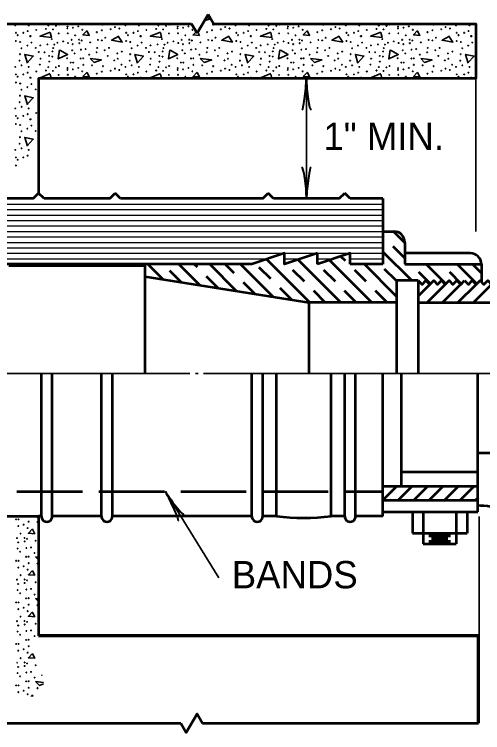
# Model space of a CAD drawing. Extents: x -1 to 679, y 0 to 440.
# Drawn here: x 158 to 200.8, y 293.5 to 359.2 of the extents above; entities that cross this region are included whole.
import ezdxf

# ---------------------------------------------------------------- set-up
doc = ezdxf.new("R2010")
doc.units = 0
doc.linetypes.add('LONG_DASHED', pattern=[7.5, 6, -1.5])
doc.linetypes.add('SHORT_DASHED', pattern=[2.7, 1.5, -1.2])
doc.layers.add('1', color=7, linetype='Continuous', lineweight=35)

msp = doc.modelspace()

# ---------------------------------------------------------------- linework, layer by layer
at = {"layer": '1', "lineweight": 53}
for p, q in [((174.684, 357.51), (175.684, 359.242)), ((176.184, 358.376), (175.684, 359.242)), ((153.184, 358.376), (174.184, 358.376)), ((174.684, 357.51), (174.184, 358.376)), ((159.684, 342.376), (160.184, 342.876)), ((160.684, 342.376), (160.184, 342.876)), ((166.684, 342.376), (167.184, 342.876)), ((167.684, 342.376), (167.184, 342.876)), ((180.684, 342.376), (181.184, 342.876)), ((181.684, 342.376), (181.184, 342.876)), ((187.684, 342.376), (188.184, 342.876)), ((188.684, 342.376), (188.184, 342.876)), ((159.684, 342.376), (146.684, 342.376)), ((166.684, 342.376), (160.684, 342.376)), ((180.684, 342.376), (167.684, 342.376)), ((187.684, 342.376), (181.684, 342.376)), ((191.684, 342.376), (188.684, 342.376)), ((191.684, 342.376), (191.684, 336.376)), ((191.684, 339.376), (192.684, 339.376)), ((193.673, 338.337), (192.637, 339.373)), ((193.684, 338.376), (193.684, 336.376)), ((185.684, 336.376), (185.684, 337.376)), ((194.308, 334.873), (191.673, 337.508)), ((199.684, 337.376), (193.684, 337.376)), ((184.995, 332.873), (181.039, 336.828)), ((187.823, 332.873), (183.911, 336.786)), ((190.652, 332.873), (186.782, 336.743)), ((179.684, 336.376), (147.684, 336.376)), ((157.463, 336.251), (169.905, 336.251)), ((169.905, 336.251), (169.905, 326.376)), ((171.572, 334.983), (170.181, 336.373)), ((174.932, 334.45), (173.01, 336.373)), ((178.293, 333.918), (175.838, 336.373)), ((181.653, 333.386), (178.666, 336.373)), ((191.684, 336.376), (188.684, 336.376)), ((192.894, 333.459), (189.98, 336.373)), ((193.684, 336.376), (200.684, 336.376)), ((197.43, 334.58), (195.637, 336.373)), ((200.258, 334.58), (198.465, 336.373)), ((200.684, 336.376), (200.684, 334.754)), ((169.905, 335.251), (184.905, 332.876)), ((194.905, 334.876), (192.905, 334.876)), ((192.905, 334.876), (192.905, 326.376)), ((194.905, 334.876), (194.905, 326.376)), ((198.795, 334.522), (199.148, 334.876)), ((195.958, 334.515), (194.907, 333.464)), ((197.372, 334.515), (195.716, 332.859)), ((198.787, 334.515), (197.13, 332.859)), ((200.201, 334.515), (198.544, 332.859)), ((201.615, 334.515), (199.958, 332.859)), ((192.905, 332.876), (184.905, 332.876)), ((184.905, 332.876), (184.905, 326.376)), ((194.905, 332.876), (224.905, 332.876)), ((160.434, 313.316), (160.434, 326.376)), ((161.434, 313.316), (161.434, 326.376)), ((165.934, 313.316), (165.934, 326.376)), ((166.934, 313.316), (166.934, 326.376)), ((179.684, 313.316), (179.684, 326.376)), ((180.684, 313.316), (180.684, 326.376)), ((181.934, 313.316), (181.934, 326.376)), ((186.934, 313.316), (186.934, 326.376)), ((188.184, 313.316), (188.184, 326.376)), ((189.184, 313.316), (189.184, 326.376)), ((191.684, 313.316), (191.684, 326.376)), ((193.369, 316.034), (193.369, 326.376)), ((200.369, 316.327), (200.369, 326.376)), ((200.434, 319.126), (222.934, 319.126)), ((200.369, 317.336), (193.369, 317.336)), ((200.369, 313.731), (200.369, 316.327)), ((191.666, 314.784), (192.916, 316.034)), ((200.434, 316.034), (191.684, 316.034)), ((193.08, 314.784), (194.33, 316.034)), ((194.494, 314.784), (195.744, 316.034)), ((195.909, 314.784), (197.159, 316.034)), ((197.323, 314.784), (198.573, 316.034)), ((198.737, 314.784), (199.987, 316.034)), ((200.151, 314.784), (200.434, 315.067)), ((191.684, 314.784), (200.434, 314.784)), ((191.684, 313.731), (200.369, 313.731)), ((194.369, 313.778), (194.369, 311.778)), ((195.369, 313.778), (195.369, 310.778)), ((198.369, 313.778), (198.369, 310.778)), ((199.369, 313.778), (199.369, 311.778)), ((160.434, 313.316), (160.184, 313.316)), ((165.934, 313.316), (161.434, 313.316)), ((179.684, 313.316), (166.934, 313.316)), ((181.934, 313.316), (180.684, 313.316)), ((188.184, 313.316), (186.934, 313.316)), ((191.684, 313.316), (189.184, 313.316)), ((194.369, 311.778), (199.369, 311.778)), ((195.869, 311.528), (197.869, 311.528)), ((195.869, 311.028), (197.869, 311.028)), ((196.119, 311.278), (197.619, 311.278)), ((195.369, 310.778), (198.369, 310.778)), ((140.184, 294.376), (173.184, 294.376)), ((175.184, 294.376), (200.409, 294.376))]:
    msp.add_line(p, q, dxfattribs=at)
at = {"layer": '1'}
for p, q in [((175.508, 358.936), (175.886, 358.893)), ((161.343, 353.376), (161.256, 353.778)), ((171.423, 353.376), (171.336, 353.778)), ((181.503, 353.376), (181.416, 353.778)), ((191.583, 353.376), (191.496, 353.778)), ((167.516, 353.438), (167.402, 353.376)), ((167.528, 353.376), (167.476, 353.458)), ((177.596, 353.438), (177.482, 353.376)), ((177.608, 353.376), (177.556, 353.458)), ((184.684, 342.376), (184.684, 353.376)), ((187.676, 353.438), (187.562, 353.376)), ((187.688, 353.376), (187.636, 353.458)), ((197.756, 353.438), (197.642, 353.376)), ((197.768, 353.376), (197.716, 353.458)), ((200.184, 353.376), (200.184, 339.376)), ((142.088, 326.376), (174.026, 326.376)), ((174.526, 326.376), (174.776, 326.376)), ((175.276, 326.376), (181.934, 326.376)), ((171.782, 315.566), (176.655, 307.674)), ((160.184, 313.115), (159.984, 313.316)), ((200.475, 302.376), (200.475, 313.277)), ((159.904, 309.596), (160.184, 309.563)), ((160.184, 309.315), (159.904, 309.596)), ((159.904, 305.796), (160.184, 305.763)), ((160.184, 305.515), (159.904, 305.796)), ((159.904, 298.196), (160.626, 298.112)), ((159.624, 296.956), (159.484, 296.808)), ((159.668, 296.828), (159.624, 296.916))]:
    msp.add_line(p, q, dxfattribs=at)
at = {"layer": '1', "lineweight": 25}
for p, q in [((135.684, 341.876), (191.684, 341.876)), ((135.684, 341.376), (191.684, 341.376)), ((135.684, 340.876), (191.684, 340.876)), ((135.684, 340.376), (191.684, 340.376)), ((135.684, 339.876), (191.684, 339.876)), ((135.684, 339.376), (191.684, 339.376)), ((135.684, 338.876), (191.684, 338.876)), ((135.684, 338.376), (191.684, 338.376)), ((135.684, 337.876), (191.684, 337.876)), ((135.684, 337.376), (191.684, 337.376)), ((146.184, 336.876), (181.184, 336.876)), ((182.684, 336.876), (184.184, 336.876)), ((185.684, 336.876), (187.184, 336.876)), ((188.684, 336.876), (191.684, 336.876))]:
    msp.add_line(p, q, dxfattribs=at)
at = {"layer": '1', "linetype": 'SHORT_DASHED', "lineweight": 53}
for p, q in [((193.673, 336.923), (191.673, 338.923)), ((192.066, 332.873), (187.843, 337.096)), ((173.252, 334.716), (171.595, 336.373)), ((176.612, 334.184), (174.424, 336.373)), ((179.973, 333.652), (177.252, 336.373)), ((183.333, 333.12), (179.979, 336.475)), ((186.409, 332.873), (182.85, 336.432)), ((189.237, 332.873), (185.721, 336.389)), ((192.894, 334.873), (191.394, 336.373)), ((196.016, 334.58), (194.223, 336.373)), ((198.844, 334.58), (197.051, 336.373)), ((200.673, 335.579), (199.88, 336.373))]:
    msp.add_line(p, q, dxfattribs=at)
at = {"layer": '1', "linetype": 'LONG_DASHED', "lineweight": 53}
msp.add_line((135.684, 315.566), (191.684, 315.566), dxfattribs=at)
at = {"layer": '1', "lineweight": 70}
for p, q in [((200.409, 302.376), (160.184, 302.376)), ((200.409, 294.376), (200.409, 302.376))]:
    msp.add_line(p, q, dxfattribs=at)
at = {"layer": '1', "lineweight": 53}
for points in [[(176.184, 358.376), (200.184, 358.376), (200.184, 353.376), (160.184, 353.376), (160.184, 342.876)], [(185.684, 337.376), (182.684, 336.376), (182.684, 337.376), (179.684, 336.376)], [(188.684, 336.376), (188.684, 337.376), (185.684, 336.376)], [(194.905, 334.876), (195.259, 334.522), (195.613, 334.876), (195.966, 334.522), (196.32, 334.876), (196.673, 334.522), (197.027, 334.876), (197.38, 334.522), (197.734, 334.876), (198.088, 334.522), (198.441, 334.876), (198.795, 334.522)], [(199.148, 334.876), (199.502, 334.522), (199.856, 334.876), (200.209, 334.522), (200.563, 334.876), (200.916, 334.522), (201.27, 334.876), (201.624, 334.522), (201.977, 334.876), (202.331, 334.522), (202.684, 334.876)], [(149.22, 313.316), (160.184, 313.316), (160.184, 302.376)], [(173.184, 294.376), (173.684, 293.51), (174.684, 295.242), (175.184, 294.376)]]:
    msp.add_lwpolyline(points, dxfattribs=at)
at = {"layer": '1'}
for points in [[(175.915, 358.842), (175.336, 358.638), (175.336, 358.638)], [(161.256, 357.618), (160.316, 357.238), (161.356, 357.118), (161.256, 357.578)], [(164.616, 357.758), (164.236, 357.358), (164.816, 357.318), (164.616, 357.718)], [(171.336, 357.618), (170.396, 357.238), (171.436, 357.118), (171.336, 357.578)], [(174.6, 357.657), (174.316, 357.358), (174.896, 357.318), (174.746, 357.617)], [(181.416, 357.618), (180.476, 357.238), (181.516, 357.118), (181.416, 357.578)], [(184.776, 357.758), (184.396, 357.358), (184.976, 357.318), (184.776, 357.718)], [(191.496, 357.618), (190.556, 357.238), (191.596, 357.118), (191.496, 357.578)], [(194.856, 357.758), (194.476, 357.358), (195.056, 357.318), (194.856, 357.718)], [(167.516, 357.238), (166.856, 356.878), (167.836, 356.698), (167.476, 357.258)], [(177.596, 357.238), (176.936, 356.878), (177.916, 356.698), (177.556, 357.258)], [(187.676, 357.238), (187.016, 356.878), (187.996, 356.698), (187.636, 357.258)], [(197.756, 357.238), (197.096, 356.878), (198.076, 356.698), (197.716, 357.258)], [(162.136, 355.978), (162.836, 355.578), (161.976, 355.158), (162.096, 355.998)], [(172.216, 355.978), (172.916, 355.578), (172.056, 355.158), (172.176, 355.998)], [(182.296, 355.978), (182.996, 355.578), (182.136, 355.158), (182.256, 355.998)], [(192.376, 355.978), (193.076, 355.578), (192.216, 355.158), (192.336, 355.998)], [(159.156, 354.778), (158.916, 355.578), (159.696, 355.418), (159.136, 354.818)], [(169.236, 354.778), (168.996, 355.578), (169.776, 355.418), (169.216, 354.818)], [(179.316, 354.778), (179.076, 355.578), (179.856, 355.418), (179.296, 354.818)], [(189.396, 354.778), (189.156, 355.578), (189.936, 355.418), (189.376, 354.818)], [(199.476, 354.778), (199.236, 355.578), (200.016, 355.418), (199.456, 354.818)], [(161.256, 353.818), (160.316, 353.438), (160.854, 353.376)], [(164.616, 353.958), (164.236, 353.558), (164.816, 353.518), (164.616, 353.918)], [(171.336, 353.818), (170.396, 353.438), (170.934, 353.376)], [(174.696, 353.958), (174.316, 353.558), (174.896, 353.518), (174.696, 353.918)], [(181.416, 353.818), (180.476, 353.438), (181.014, 353.376)], [(184.776, 353.958), (184.396, 353.558), (184.976, 353.518), (184.776, 353.918)], [(191.496, 353.818), (190.556, 353.438), (191.094, 353.376)], [(194.856, 353.958), (194.476, 353.558), (195.056, 353.518), (194.856, 353.918)], [(159.156, 350.978), (158.916, 351.778), (159.696, 351.618), (159.136, 351.018)], [(159.156, 347.178), (158.916, 347.978), (159.696, 347.818), (159.136, 347.218)], [(181.934, 326.376), (194.905, 326.376), (200.434, 326.376), (208.434, 326.376)], [(159.624, 312.156), (159.244, 311.756), (159.824, 311.716), (159.624, 312.116)], [(159.624, 308.356), (159.244, 307.956), (159.824, 307.916), (159.624, 308.316)], [(159.624, 304.556), (159.244, 304.156), (159.824, 304.116), (159.624, 304.516)], [(159.624, 300.756), (159.244, 300.356), (159.824, 300.316), (159.624, 300.716)], [(160.641, 297.969), (160.264, 297.836), (159.904, 298.196)]]:
    msp.add_lwpolyline(points, dxfattribs=at)
for points in [[(164.896, 355.198), (165.936, 355.078), (165.256, 354.838)], [(174.976, 355.198), (176.016, 355.078), (175.336, 354.838)], [(185.056, 355.198), (186.096, 355.078), (185.416, 354.838)], [(195.136, 355.198), (196.176, 355.078), (195.496, 354.838)]]:
    msp.add_lwpolyline(points, close=True, dxfattribs=at)
for centre in [(158.044, 358.234), (159.277, 358.234), (161.066, 358.221), (162.046, 358.314), (166.07, 358.301), (168.124, 358.234), (169.357, 358.234), (171.146, 358.221), (172.126, 358.314), (176.15, 358.301), (178.204, 358.234), (179.437, 358.234), (181.226, 358.221), (182.206, 358.314), (186.23, 358.301), (188.284, 358.234), (189.517, 358.234), (191.306, 358.221), (192.286, 358.314), (196.31, 358.301), (198.364, 358.234), (199.597, 358.234), (159.184, 357.709), (159.966, 357.815), (160.854, 357.908), (161.49, 357.868), (161.768, 358.195), (162.815, 357.961), (162.828, 358.128), (163.319, 358.014), (163.809, 358.142), (164.175, 357.828), (165.513, 357.616), (165.964, 357.789), (166.772, 357.881), (167.17, 358.075), (167.567, 357.948), (169.264, 357.709), (170.046, 357.815), (170.934, 357.908), (171.57, 357.868), (171.848, 358.195), (172.895, 357.961), (172.908, 358.128), (173.399, 358.014), (173.889, 358.142), (174.255, 357.828), (175.593, 357.616), (176.044, 357.789), (176.852, 357.881), (177.25, 358.075), (177.647, 357.948), (179.344, 357.709), (180.126, 357.815), (181.014, 357.908), (181.65, 357.868), (181.928, 358.195), (182.975, 357.961), (182.988, 358.128), (183.479, 358.014), (183.969, 358.142), (184.335, 357.828), (185.673, 357.616), (186.124, 357.789), (186.932, 357.881), (187.33, 358.075), (187.727, 357.948), (189.424, 357.709), (190.206, 357.815), (191.094, 357.908), (191.73, 357.868), (192.008, 358.195), (193.055, 357.961), (193.068, 358.128), (193.559, 358.014), (194.049, 358.142), (194.415, 357.828), (195.753, 357.616), (196.204, 357.789), (197.012, 357.881), (197.41, 358.075), (197.807, 357.948), (199.504, 357.709), (158.11, 357.55), (158.269, 357.338), (158.786, 357.55), (159.409, 357.245), (159.462, 357.245), (161.384, 356.98), (162.02, 357.497), (162.855, 357.51), (163.199, 356.914), (163.531, 357.325), (163.889, 356.927), (165.619, 356.9), (166.282, 357.099), (168.19, 357.55), (168.349, 357.338), (168.866, 357.55), (169.489, 357.245), (169.542, 357.245), (171.464, 356.98), (172.1, 357.497), (172.935, 357.51), (173.279, 356.914), (173.611, 357.325), (173.969, 356.927), (175.699, 356.9), (176.362, 357.099), (178.27, 357.55), (178.429, 357.338), (178.946, 357.55), (179.569, 357.245), (179.622, 357.245), (181.544, 356.98), (182.18, 357.497), (183.015, 357.51), (183.359, 356.914), (183.691, 357.325), (184.049, 356.927), (185.779, 356.9), (186.442, 357.099), (188.35, 357.55), (188.509, 357.338), (189.026, 357.55), (189.649, 357.245), (189.702, 357.245), (191.624, 356.98), (192.26, 357.497), (193.095, 357.51), (193.439, 356.914), (193.771, 357.325), (194.129, 356.927), (195.859, 356.9), (196.522, 357.099), (198.43, 357.55), (198.589, 357.338), (199.106, 357.55), (199.729, 357.245), (199.782, 357.245), (158.11, 356.808), (158.495, 356.715), (159.157, 356.383), (159.528, 356.662), (160.337, 356.397), (160.986, 356.489), (161.622, 356.476), (161.901, 356.648), (162.431, 356.768), (162.881, 356.622), (163.306, 356.516), (163.902, 356.609), (164.122, 356.847), (164.903, 356.675), (165.964, 356.861), (168.19, 356.808), (168.575, 356.715), (169.237, 356.383), (169.608, 356.662), (170.417, 356.397), (171.066, 356.489), (171.702, 356.476), (171.981, 356.648), (172.511, 356.768), (172.961, 356.622), (173.386, 356.516), (173.982, 356.609), (174.202, 356.847), (174.983, 356.675), (176.044, 356.861), (178.27, 356.808), (178.655, 356.715), (179.317, 356.383), (179.688, 356.662), (180.497, 356.397), (181.146, 356.489), (181.782, 356.476), (182.061, 356.648), (182.591, 356.768), (183.041, 356.622), (183.466, 356.516), (184.062, 356.609), (184.282, 356.847), (185.063, 356.675), (186.124, 356.861), (188.35, 356.808), (188.735, 356.715), (189.397, 356.383), (189.768, 356.662), (190.577, 356.397), (191.226, 356.489), (191.862, 356.476), (192.141, 356.648), (192.671, 356.768), (193.121, 356.622), (193.546, 356.516), (194.142, 356.609), (194.362, 356.847), (195.143, 356.675), (196.204, 356.861), (198.43, 356.808), (198.815, 356.715), (199.477, 356.383), (199.848, 356.662), (158.481, 355.601), (158.614, 356.145), (159.926, 356.171), (160.204, 355.8), (160.721, 355.773), (161.45, 355.853), (161.516, 356.158), (163.252, 355.959), (163.478, 355.667), (164.061, 356.012), (164.479, 356.065), (165.487, 355.773), (165.54, 356.171), (166.229, 355.959), (166.626, 356.171), (167.382, 355.667), (167.793, 355.84), (168.561, 355.601), (168.694, 356.145), (170.006, 356.171), (170.284, 355.8), (170.801, 355.773), (171.53, 355.853), (171.596, 356.158), (173.332, 355.959), (173.558, 355.667), (174.141, 356.012), (174.559, 356.065), (175.567, 355.773), (175.62, 356.171), (176.309, 355.959), (176.706, 356.171), (177.462, 355.667), (177.873, 355.84), (178.641, 355.601), (178.774, 356.145), (180.086, 356.171), (180.364, 355.8), (180.881, 355.773), (181.61, 355.853), (181.676, 356.158), (183.412, 355.959), (183.638, 355.667), (184.221, 356.012), (184.639, 356.065), (185.647, 355.773), (185.7, 356.171), (186.389, 355.959), (186.786, 356.171), (187.542, 355.667), (187.953, 355.84), (188.721, 355.601), (188.854, 356.145), (190.166, 356.171), (190.444, 355.8), (190.961, 355.773), (191.69, 355.853), (191.756, 356.158), (193.492, 355.959), (193.718, 355.667), (194.301, 356.012), (194.719, 356.065), (195.727, 355.773), (195.78, 356.171), (196.469, 355.959), (196.866, 356.171), (197.622, 355.667), (198.033, 355.84), (198.801, 355.601), (198.934, 356.145), (158.442, 355.005), (160.363, 355.19), (161.145, 355.442), (161.437, 355.376), (162.789, 355.23), (164.041, 355.201), (164.267, 355.217), (164.811, 355.548), (166.507, 355.442), (167.104, 355.031), (167.422, 355.177), (168.522, 355.005), (170.443, 355.19), (171.225, 355.442), (171.517, 355.376), (172.869, 355.23), (174.121, 355.201), (174.347, 355.217), (174.891, 355.548), (176.587, 355.442), (177.184, 355.031), (177.502, 355.177), (178.602, 355.005), (180.523, 355.19), (181.305, 355.442), (181.597, 355.376), (182.949, 355.23), (184.201, 355.201), (184.427, 355.217), (184.971, 355.548), (186.667, 355.442), (187.264, 355.031), (187.582, 355.177), (188.682, 355.005), (190.603, 355.19), (191.385, 355.442), (191.677, 355.376), (193.029, 355.23), (194.281, 355.201), (194.507, 355.217), (195.051, 355.548), (196.747, 355.442), (197.344, 355.031), (197.662, 355.177), (198.762, 355.005), (158.044, 354.434), (158.627, 354.58), (159.277, 354.434), (160.297, 354.647), (161.066, 354.421), (161.159, 354.925), (161.768, 354.395), (162.046, 354.514), (162.828, 354.328), (163.12, 354.832), (163.345, 354.832), (163.809, 354.342), (164.267, 354.62), (165.076, 354.58), (166.07, 354.501), (167.17, 354.275), (167.766, 354.633), (168.124, 354.434), (168.707, 354.58), (169.357, 354.434), (170.377, 354.647), (171.146, 354.421), (171.239, 354.925), (171.848, 354.395), (172.126, 354.514), (172.908, 354.328), (173.2, 354.832), (173.425, 354.832), (173.889, 354.342), (174.347, 354.62), (175.156, 354.58), (176.15, 354.501), (177.25, 354.275), (177.846, 354.633), (178.204, 354.434), (178.787, 354.58), (179.437, 354.434), (180.457, 354.647), (181.226, 354.421), (181.319, 354.925), (181.928, 354.395), (182.206, 354.514), (182.988, 354.328), (183.28, 354.832), (183.505, 354.832), (183.969, 354.342), (184.427, 354.62), (185.236, 354.58), (186.23, 354.501), (187.33, 354.275), (187.926, 354.633), (188.284, 354.434), (188.867, 354.58), (189.517, 354.434), (190.537, 354.647), (191.306, 354.421), (191.399, 354.925), (192.008, 354.395), (192.286, 354.514), (193.068, 354.328), (193.36, 354.832), (193.585, 354.832), (194.049, 354.342), (194.507, 354.62), (195.316, 354.58), (196.31, 354.501), (197.41, 354.275), (198.006, 354.633), (198.364, 354.434), (198.947, 354.58), (199.597, 354.434), (158.11, 353.75), (158.786, 353.75), (159.184, 353.909), (159.966, 354.015), (160.854, 354.108), (161.49, 354.068), (162.02, 353.697), (162.815, 354.161), (162.855, 353.71), (163.319, 354.214), (164.175, 354.028), (165.513, 353.816), (165.964, 353.989), (166.772, 354.081), (167.567, 354.148), (168.19, 353.75), (168.866, 353.75), (169.264, 353.909), (170.046, 354.015), (170.934, 354.108), (171.57, 354.068), (172.1, 353.697), (172.895, 354.161), (172.935, 353.71), (173.399, 354.214), (174.255, 354.028), (175.593, 353.816), (176.044, 353.989), (176.852, 354.081), (177.647, 354.148), (178.27, 353.75), (178.946, 353.75), (179.344, 353.909), (180.126, 354.015), (181.014, 354.108), (181.65, 354.068), (182.18, 353.697), (182.975, 354.161), (183.015, 353.71), (183.479, 354.214), (184.335, 354.028), (185.673, 353.816), (186.124, 353.989), (186.932, 354.081), (187.727, 354.148), (188.35, 353.75), (189.026, 353.75), (189.424, 353.909), (190.206, 354.015), (191.094, 354.108), (191.73, 354.068), (192.26, 353.697), (193.055, 354.161), (193.095, 353.71), (193.559, 354.214), (194.415, 354.028), (195.753, 353.816), (196.204, 353.989), (197.012, 354.081), (197.807, 354.148), (198.43, 353.75), (199.106, 353.75), (199.504, 353.909), (158.11, 353.008), (158.269, 353.538), (159.409, 353.445), (159.462, 353.445), (163.531, 353.525), (168.349, 353.538), (169.489, 353.445), (169.542, 353.445), (173.611, 353.525), (178.429, 353.538), (179.569, 353.445), (179.622, 353.445), (183.691, 353.525), (188.509, 353.538), (189.649, 353.445), (189.702, 353.445), (193.771, 353.525), (198.589, 353.538), (199.729, 353.445), (199.782, 353.445), (158.495, 352.915), (158.614, 352.345), (159.157, 352.583), (159.528, 352.862), (159.926, 352.371), (158.481, 351.801), (158.442, 351.205), (158.044, 350.634), (158.627, 350.78), (159.277, 350.634), (158.11, 349.95), (158.269, 349.738), (158.786, 349.95), (159.184, 350.109), (159.966, 350.215), (158.11, 349.208), (158.495, 349.115), (159.409, 349.645), (159.462, 349.645), (159.528, 349.062), (158.614, 348.545), (159.157, 348.783), (159.926, 348.571), (158.481, 348.001), (158.442, 347.405), (158.044, 346.834), (158.627, 346.98), (159.277, 346.834), (158.11, 346.15), (158.269, 345.938), (158.786, 346.15), (159.184, 346.309), (158.11, 345.408), (158.128, 313.03), (158.354, 313.03), (158.327, 312.412), (158.817, 312.539), (159.183, 312.226), (159.276, 312.818), (160.084, 312.778), (158.539, 311.722), (158.208, 311.311), (158.314, 310.914), (158.897, 311.325), (158.91, 311.006), (159.13, 311.245), (159.912, 311.073), (158.261, 310.357), (159.069, 310.41), (159.488, 310.463), (158.486, 310.065), (159.049, 309.599), (159.276, 309.614), (159.819, 309.946), (158.128, 309.23), (158.354, 309.23), (159.276, 309.018), (160.084, 308.978), (158.327, 308.612), (158.817, 308.739), (159.183, 308.426), (158.539, 307.922), (158.208, 307.511), (158.314, 307.114), (158.897, 307.525), (158.91, 307.206), (159.13, 307.445), (159.912, 307.273), (158.261, 306.557), (159.069, 306.61), (159.488, 306.663), (158.486, 306.265), (159.049, 305.799), (159.276, 305.814), (159.819, 306.146), (158.128, 305.43), (158.354, 305.43), (159.276, 305.218), (160.084, 305.178), (158.327, 304.812), (158.817, 304.939), (159.183, 304.626), (158.208, 303.711), (158.539, 304.122), (158.897, 303.725), (158.314, 303.314), (158.91, 303.406), (159.13, 303.645), (159.912, 303.473), (158.261, 302.757), (158.486, 302.465), (159.069, 302.81), (159.488, 302.863), (159.819, 302.346), (159.049, 301.999), (159.276, 302.014), (158.128, 301.63), (158.354, 301.63), (158.817, 301.139), (159.276, 301.418), (158.327, 301.012), (159.183, 300.826), (158.539, 300.322), (158.897, 299.925), (159.13, 299.845), (158.314, 299.514), (158.91, 299.606), (159.488, 299.063), (159.912, 299.673), (158.261, 298.957), (158.486, 298.665), (159.069, 299.01), (159.819, 298.546), (158.128, 297.83), (158.354, 297.83), (159.049, 298.199), (159.276, 298.214), (158.327, 297.212), (158.817, 297.339), (159.276, 297.618), (160.084, 297.578), (159.183, 297.026)]:
    msp.add_circle(centre, 0.0265, dxfattribs=at)
for centre, start, end in [((158.627, 358.38), 189.85166, 350.14834), ((165.076, 358.38), 189.85166, 350.14834), ((168.707, 358.38), 189.85166, 350.14834), ((178.787, 358.38), 189.85166, 350.14834), ((185.236, 358.38), 189.85166, 350.14834), ((188.867, 358.38), 189.85166, 350.14834), ((195.316, 358.38), 189.85166, 350.14834), ((198.947, 358.38), 189.85166, 350.14834), ((160.204, 352), 139.14202, 220.85798), ((160.204, 348.2), 139.14202, 220.85798), ((158.208, 299.911), 211.9828, 149.64303), ((160.495, 298.771), 129.87991, 264.14833)]:
    msp.add_arc(centre, 0.0265, start, end, dxfattribs=at)
at = {"layer": '1', "lineweight": 53}
for centre, radius, start, end in [((192.684, 338.376), 1, 0, 90), ((199.684, 336.376), 1, 0, 90), ((160.934, 313.307), 0.5, 178.95622, 1.04378), ((166.434, 313.307), 0.5, 178.95622, 1.04378), ((180.184, 313.307), 0.5, 178.95622, 1.04378), ((184.434, 333.664), 20.502, 262.99578, 277.00423), ((188.684, 313.307), 0.5, 178.95622, 1.04378)]:
    msp.add_arc(centre, radius, start, end, dxfattribs=at)
at = {"layer": '1', "lineweight": 40}
for centre, major_axis, ratio, start_param, end_param in [((184.473, 352.255), (0.176, 1.756), 0.07063, 3.140715, 5.41811), ((184.473, 352.255), (0.176, 1.756), 0.07063, 3.140715, 5.41811), ((184.961, 352.285), (-0.156, 1.786), 0.122415, 0.896353, 3.141593), ((184.961, 352.285), (-0.156, 1.786), 0.122415, 0.896353, 3.141593), ((184.408, 343.467), (0.156, -1.786), 0.122415, 0.896353, 3.141593), ((184.896, 343.496), (-0.176, -1.756), 0.07063, 3.140715, 5.41811), ((172.191, 314.501), (0.773, -1.587), 0.07063, 6.282307, 8.559703), ((172.591, 314.783), (-1.071, 1.437), 0.122415, 0.896353, 3.141593)]:
    msp.add_ellipse(centre, major_axis=major_axis, ratio=ratio, start_param=start_param, end_param=end_param, dxfattribs=at)
at = {"layer": '1', "lineweight": 53}
msp.add_spline([(200.28, 314.316), (202.747, 313.861), (204.76, 311.263), (203.526, 307.885), (203.072, 304.897), (204.76, 304.573), (206.059, 305.612), (207.422, 307.755), (208.591, 308.665), (209.955, 307.69), (208.591, 305.807), (208.266, 304.378), (208.396, 303.144), (209.825, 302.754), (212.357, 304.313), (214.24, 306.911), (217.422, 308.405), (222.811, 309.249), (227.934, 308.626)], degree=3, dxfattribs=at)

# ---------------------------------------------------------------- texts
at = {"layer": '1'}
for s, p in [('1" MIN.', (186.233, 346.835)), ('BANDS', (177.852, 306.716))]:
    msp.add_text(s, height=2.5, dxfattribs=at).set_placement(p)

doc.saveas('drawing.dxf')
